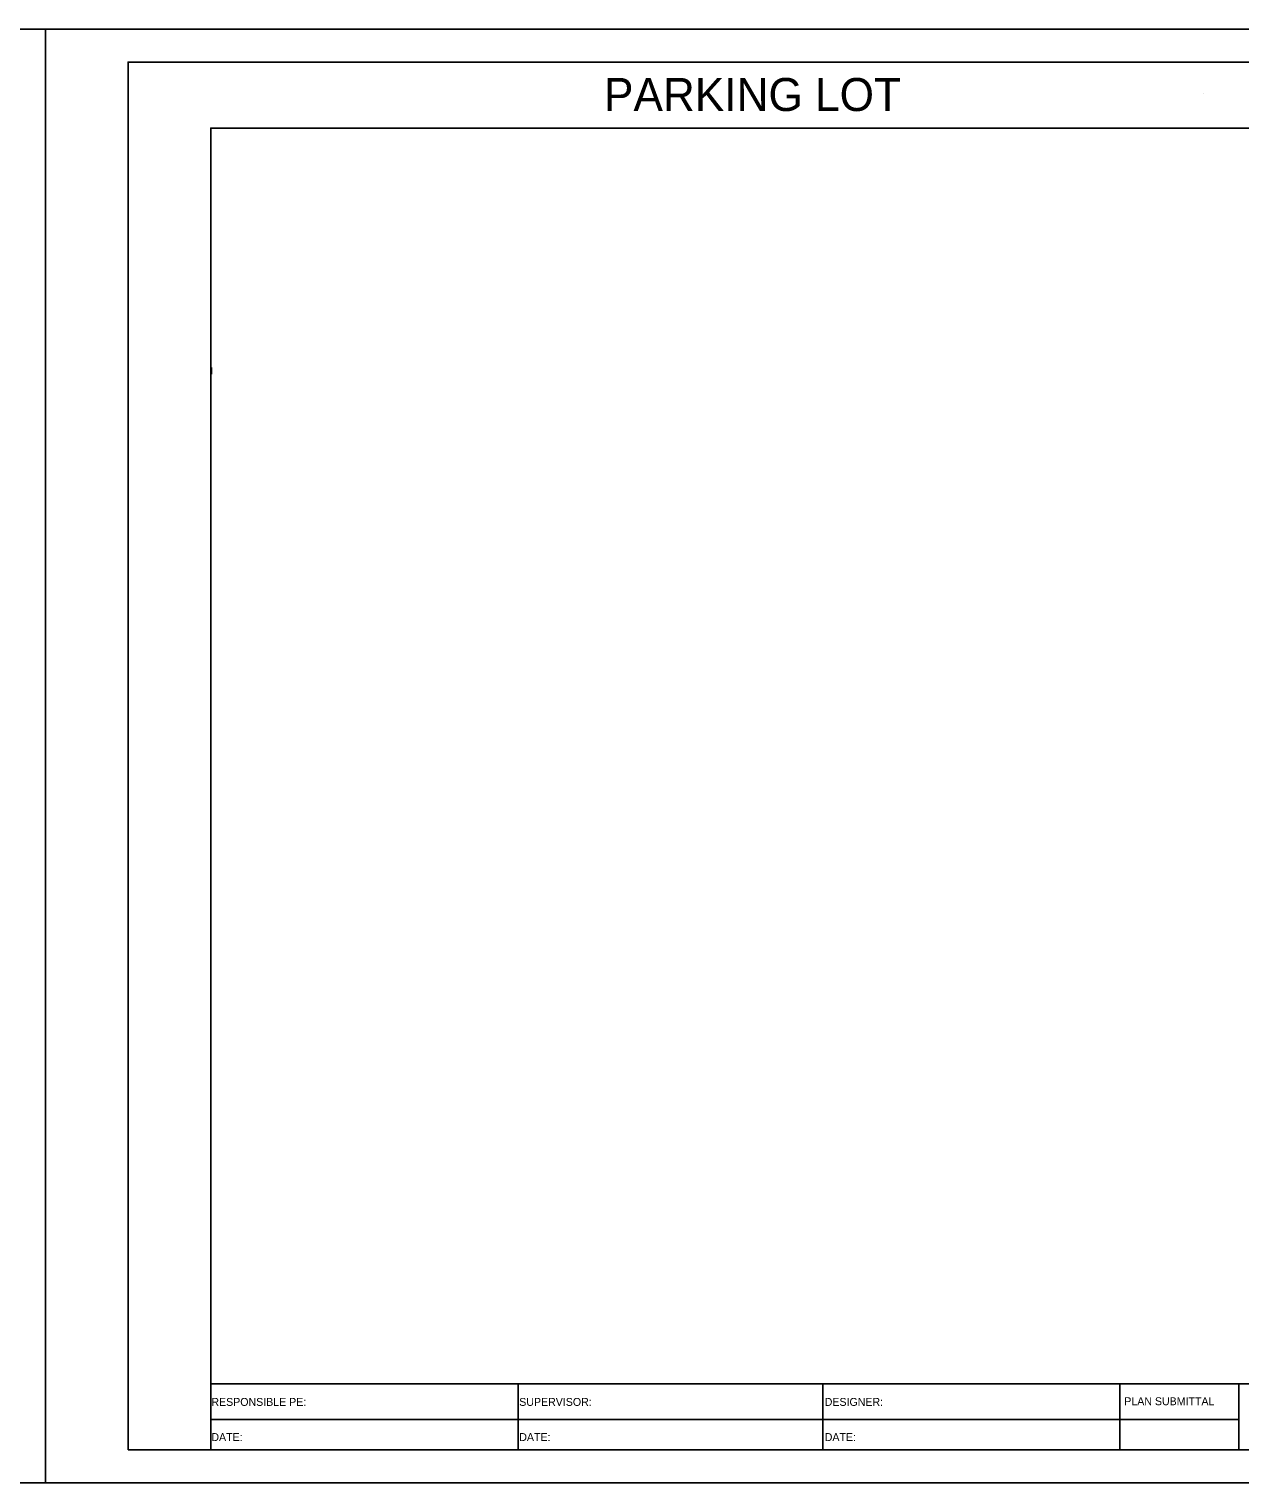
# Model space of a CAD drawing. Extents: x 1797478 to 1802796, y 246529 to 250952.
# Drawn here: x 1802453.5 to 1802636.8, y 250064.4 to 250284.4 of the extents above; entities that cross this region are included whole.
import ezdxf

# ---------------------------------------------------------------- set-up
doc = ezdxf.new("R2010")
doc.units = 0
for name, color, linetype in [('2', 7, 'Continuous'), ('ANNO-SHT', 7, 'Continuous'), ('ANNO-TXT', 7, 'Continuous'), ('AXIS', 7, 'Continuous'), ('DRAINAGE', 7, 'Continuous'), ('Level 1', 7, 'Continuous'), ('Level 62', 7, 'Continuous'), ('SHT-BDR', 7, 'Continuous'), ('SHT-BNDRY', 7, 'Continuous')]:
    doc.layers.add(name, color=color, linetype=linetype)

# ---------------------------------------------------------------- blocks, each defined once
blk = doc.blocks.new('SC47208')
at = {"layer": 'Level 1'}
blk.add_line((0, 0), (0, 0), dxfattribs=at)

msp = doc.modelspace()

# ---------------------------------------------------------------- linework, layer by layer
at = {"layer": '2'}
msp.add_lwpolyline([(1802481.12, 250233.21), (1802481.1, 250232.21)], dxfattribs=at)
msp.add_lwpolyline([(1802481.12, 250233.21), (1802481.1, 250232.21)], dxfattribs=at)
at = {"layer": 'AXIS'}
msp.add_line((1802481, 250189.42), (1802481, 250189.43), dxfattribs=at)
at = {"layer": 'Level 62'}
for points in [[(1802116, 250064.42), (1802456, 250064.42), (1802456, 250284.42), (1802116, 250284.42)], [(1802456, 250064.42), (1802796, 250064.42), (1802796, 250284.42), (1802456, 250284.42)]]:
    msp.add_lwpolyline(points, close=True, dxfattribs=at)
at = {"layer": 'SHT-BDR'}
msp.add_lwpolyline([(1802481, 250079.43), (1802781, 250079.43), (1802781, 250269.43), (1802481, 250269.43)], close=True, dxfattribs=at)
at = {"layer": 'SHT-BNDRY'}
for p, q in [((1802481, 250069.42), (1802481, 250079.43)), ((1802527.52, 250079.43), (1802527.52, 250069.42)), ((1802573.67, 250069.42), (1802573.67, 250079.43)), ((1802618.59, 250069.42), (1802618.59, 250079.43)), ((1802636.63, 250069.42), (1802636.63, 250079.43)), ((1802481, 250074.03), (1802636.63, 250074.03))]:
    msp.add_line(p, q, dxfattribs=at)
msp.add_lwpolyline([(1802468.5, 250069.42), (1802791, 250069.42), (1802791, 250279.42), (1802468.5, 250279.42)], close=True, dxfattribs=at)

# ---------------------------------------------------------------- block references
at = {"layer": 'DRAINAGE', "xscale": 0.2, "yscale": 0.20000000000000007, "rotation": -116.41666666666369}
msp.add_blockref('SC47208', (1802631.32, 250274.62), dxfattribs=at)
msp.add_blockref('SC47208', (1802631.32, 250274.62), dxfattribs=at)

# ---------------------------------------------------------------- texts
at = {"layer": 'ANNO-SHT'}
msp.add_text('                    PARKING LOT             ', height=4.9995, rotation=360, dxfattribs=at).set_placement((1802503.38, 250272.02))
at = {"layer": 'ANNO-TXT'}
for s, p in [('RESPONSIBLE PE:', (1802481.1, 250076.08)), ('SUPERVISOR:', (1802527.7, 250076.08)), ('DESIGNER:', (1802573.94, 250076.08)), ('PLAN SUBMITTAL', (1802619.28, 250076.18)), ('DATE:', (1802481.1, 250070.76)), ('DATE:', (1802527.7, 250070.76)), ('DATE:', (1802573.94, 250070.76))]:
    msp.add_text(s, height=1.2, rotation=360, dxfattribs=at).set_placement(p)

doc.saveas('drawing.dxf')
